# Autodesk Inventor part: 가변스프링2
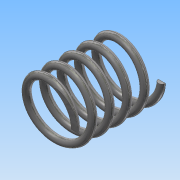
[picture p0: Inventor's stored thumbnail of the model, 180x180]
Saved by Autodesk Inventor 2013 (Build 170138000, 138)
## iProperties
Created: 2018-10
Part Number: 가변스프링2
Material: 스테인리스강
Document SubType Name: Modeling
Designer: Administrator
Density: 8.08 g/cm^3
Mass: 6.26934 g
Surface Area: 15.7569 cm^2
Volume: 0.775909 cm^3
Author: Administrator
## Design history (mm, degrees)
sketch "스케치1"
  geometry: L1 (0, 0)-(0, 24.529); L2 (0, 24.529)-(8, 24.529); L3 (0, 0)-(8, 0); C1 r 1 at (8, 0)
  constraints: 6 end point, 1 centre point, 1 horizontal alignment, 1 parallel, 1 perpendicular, 1 vertical
  dimensions: "d0" = 24.52909 distance of L1.start L1.end (derived); "d1" = 8 distance of L1.end L2.end; "d2" = 2 diameter of C1; "d3" = 16 diameter of L3.end L1
feature "코일1" sketch "스케치1" pitch "d4" = 10; turns "d6" = 5; dims "d5" = 24.52909 (= d0), "d7" = 0, angle "d8" = 90 deg, angle "d9" = 90 deg, "d10" = 0, "d11" = 0
sketch "스케치2"
  geometry: L1 (24.529, 10)-(0, 10); L2 (0, 10)-(0, -10); L3 (0, -10)-(24.529, -10); L4 (24.529, -10)-(24.529, 10); 2 further points
  constraints: 8 end point, 2 parallel, 1 coincident, 1 horizontal, 1 midpoint, 1 perpendicular
  dimensions: "d12" = 24.52909 distance of L3.end L2.end (derived); "d13" = 20 distance of L2.end L1.end
extrude "돌출1" sketch "스케치2" stored distance "d14" = 0; taper "d15" = 0 deg
node "솔리드1"
